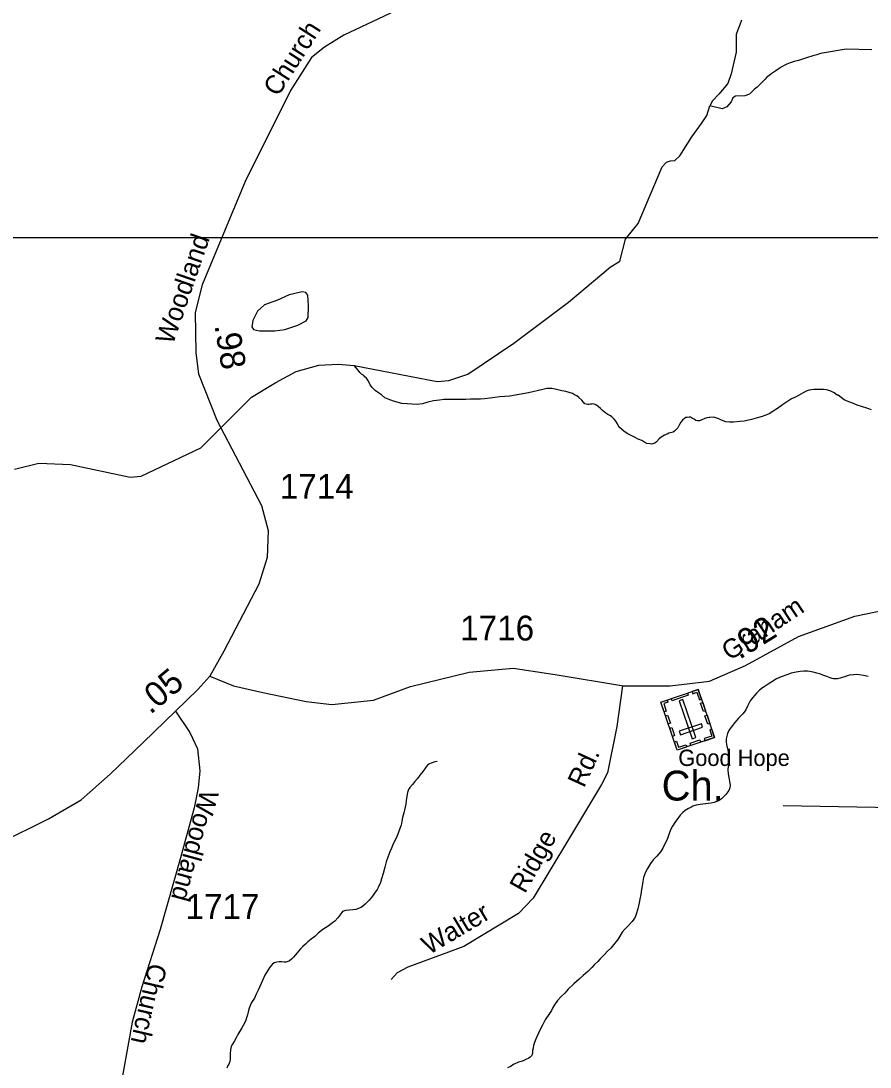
# Model space of a CAD drawing. Extents: x 2056842 to 2160602, y 826753 to 1016856.
# Drawn here: x 2126740 to 2131011, y 836629 to 841891 of the extents above; entities that cross this region are included whole.
import ezdxf

# ---------------------------------------------------------------- set-up
doc = ezdxf.new("R2010")
doc.units = 0
for name, color, linetype in [('Exist Cultural Cemetery CELL', 7, 'Continuous'), ('Exist Cultural Cemetery Label', 7, 'Continuous'), ('Exist Cultural Church with Cemetery Label', 7, 'Continuous'), ('Exist Hydrographic Creek Single Shore', 7, 'Continuous'), ('Exist Hydrographic Misc Water Feature', 7, 'Continuous'), ('Exist Road Non-System Type 51', 7, 'Continuous'), ('Exist Road Non-System Type 51 Label', 7, 'Continuous'), ('Exist Road Secondary Mileage Hundredths English Label', 7, 'Continuous'), ('Exist Road Secondary Type 41 Attributed', 7, 'Continuous'), ('Exist Road Secondary Type 51 Attributed', 7, 'Continuous'), ('Exist Road Secondary Type 51 Label', 7, 'Continuous'), ('Exist Road Secondary Type 51 Number Label', 7, 'Continuous'), ('Map Preparation Inset Cut Line', 7, 'Continuous')]:
    doc.layers.add(name, color=color, linetype=linetype)

msp = doc.modelspace()

# ---------------------------------------------------------------- linework, layer by layer
at = {"layer": 'Exist Cultural Cemetery CELL'}
for points in [[(2130229.4, 838287.4), (2130041, 838223.2), (2129958.9, 838464.3), (2130147.4, 838528.4)], [(2130096.7, 838499), (2130016.4, 838471.7), (2130012.7, 838482.5), (2130093, 838509.8)], [(2130116.1, 838517.7), (2130119.8, 838506.8), (2130140.6, 838513.9), (2130153.6, 838475.7), (2130164.2, 838479.3), (2130147.5, 838528.4)], [(2129990.3, 838474.9), (2129994, 838464.1), (2129973.2, 838457), (2129986.2, 838418.7), (2129975.6, 838415.1), (2129958.9, 838464.3)], [(2130116.8, 838280), (2130134.5, 838286), (2130069.1, 838478), (2130051.4, 838471.9)], [(2130170, 838462.2), (2130183.9, 838421.2), (2130173.1, 838417.6), (2130159.2, 838458.6)], [(2129993, 838399.5), (2130006.9, 838358.5), (2129996.2, 838354.8), (2129982.2, 838395.8)], [(2130191.6, 838398.6), (2130205.6, 838357.6), (2130194.8, 838353.9), (2130180.8, 838394.9)], [(2130014.2, 838337.1), (2130028.2, 838296.1), (2130017.4, 838292.4), (2130003.4, 838333.4)], [(2130168.9, 838338.7), (2130162.9, 838356.3), (2130051.4, 838318.4), (2130057.4, 838300.7)], [(2130215.5, 838328.4), (2130204.7, 838324.7), (2130215.1, 838294.2), (2130176.7, 838281.2), (2130180.3, 838270.6), (2130229.4, 838287.4)], [(2130026.9, 838264.2), (2130037.7, 838267.9), (2130048.1, 838237.4), (2130086.4, 838250.5), (2130090, 838240), (2130040.9, 838223.2)], [(2130159.3, 838263.5), (2130110.3, 838246.8), (2130106.6, 838257.6), (2130155.7, 838274.3)]]:
    msp.add_lwpolyline(points, close=True, dxfattribs=at)
at = {"layer": 'Exist Hydrographic Creek Single Shore'}
for points in [[(2130364.2, 841893.5), (2130356.6, 841870.8), (2130346.4, 841845.5), (2130337.4, 841821.7), (2130337.3, 841733.5), (2130313, 841624.3), (2130296.5, 841575.8), (2130250.2, 841521.8), (2130218.3, 841488.7), (2130205.7, 841463.9)], [(2131020.7, 841745.4), (2130891.7, 841748.7), (2130762.2, 841727), (2130743.8, 841720.8), (2130723.7, 841714.6), (2130691.9, 841704.8), (2130672, 841698.4), (2130651.9, 841692.2), (2130630, 841686.1), (2130609.3, 841679.1), (2130592.9, 841672.3), (2130576.4, 841665), (2130564.8, 841658.7), (2130549.4, 841648.4), (2130537.3, 841639.7), (2130526.8, 841632.4), (2130516.8, 841625.4), (2130504.1, 841615.9), (2130492.8, 841607.1), (2130484.2, 841598.2), (2130474.9, 841588.7), (2130464.7, 841578.9), (2130461.2, 841575), (2130452, 841565.8), (2130443, 841557.8), (2130436.6, 841552.3), (2130430, 841546.8), (2130405.6, 841521.5), (2130381.4, 841514), (2130334, 841512.9), (2130320.8, 841504.1), (2130313, 841484.3), (2130291, 841457.8), (2130267.9, 841449), (2130205.7, 841463.9)], [(2126707.9, 839636.5), (2126830.8, 839666.6), (2126989.2, 839659.6), (2127290.2, 839596.6), (2127344.8, 839600.8), (2127645.7, 839743.5), (2127900.6, 839997.6), (2128022.3, 840071.8), (2128124.4, 840127.8), (2128238.6, 840159.4), (2128335.9, 840164.3), (2128415.8, 840157.8), (2128834.2, 840076.7), (2128892.5, 840081.6), (2128987.3, 840113.2), (2129219.6, 840270.3), (2129495.2, 840476.9), (2129704.6, 840652.3), (2129752, 840682.5), (2129780.7, 840792.8), (2129845.7, 840871.1), (2129964.8, 841156.4), (2129987.9, 841180.7), (2130007.7, 841187.3), (2130029.8, 841188.3), (2130055.1, 841212.5), (2130114.6, 841307.4), (2130164.2, 841374.6), (2130190.7, 841415.5), (2130205.7, 841463.9)], [(2129919.5, 839763.4), (2129913.1, 839761.9), (2129905.1, 839763.9), (2129889.1, 839765.9), (2129873.1, 839773.6), (2129863.5, 839779.6), (2129845.2, 839787.2), (2129826.8, 839796.5), (2129809.1, 839805.3), (2129792.7, 839814.6), (2129774.7, 839826.3), (2129760.5, 839838.2), (2129748.4, 839849.7), (2129740.7, 839863.9), (2129732.5, 839878.1), (2129724.3, 839888.3), (2129711.7, 839899.9), (2129706, 839904), (2129691.6, 839911.9), (2129682, 839917.8), (2129665.6, 839931.3), (2129655.8, 839941.3), (2129643.9, 839951.2), (2129635.5, 839957.3), (2129629.3, 839961.5), (2129623.4, 839963.2), (2129615.6, 839964.8), (2129609.6, 839962.4), (2129605.3, 839962.7), (2129599.2, 839961.2), (2129591.4, 839960.7), (2129583.2, 839962.4), (2129577.2, 839964.9), (2129561.6, 839982.7), (2129546.9, 839996.7), (2129536.6, 840004.3), (2129524.9, 840010.6), (2129514.9, 840016.2), (2129480.9, 840026.2), (2129470.8, 840027.7), (2129461, 840029.6), (2129440.9, 840035.9), (2129426.9, 840039.2), (2129411.1, 840041.6), (2129384.9, 840042.7), (2129364.8, 840036.8), (2129293.2, 840020.1), (2129199.1, 840003.1), (2129174.9, 840001.1), (2129149.1, 839999.3), (2129123.2, 839996.3), (2129100.9, 839992.8), (2129071.2, 839990), (2129051.7, 839988.1), (2129035.5, 839987.7), (2129013.3, 839988.2), (2129001.4, 839987.6), (2128977.2, 839987.2), (2128945.3, 839987.1), (2128919.2, 839986.6), (2128891.1, 839986.4), (2128867.3, 839986), (2128845.4, 839984), (2128815.7, 839980), (2128787.6, 839973.7), (2128759.7, 839965.4), (2128735.7, 839960.9), (2128655.5, 839966.9), (2128613.7, 839978.1), (2128587.6, 839987.8), (2128571.4, 839995.5), (2128553, 840010), (2128533.1, 840023.2), (2128521.2, 840031.1), (2128506.9, 840047), (2128497, 840061.1), (2128492.9, 840069.5), (2128484.5, 840083.7), (2128478.6, 840093.5), (2128470.4, 840100.8), (2128464.6, 840107), (2128452.7, 840114.5), (2128444.3, 840123), (2128436.1, 840134.4), (2128415.8, 840157.8)], [(2131019.4, 839935.3), (2130999.5, 839941.5), (2130969.1, 839951), (2130947.2, 839958.7), (2130927.3, 839966.6), (2130905.1, 839974.5), (2130880.7, 839984.2), (2130851.2, 840007.8), (2130846.5, 840007.7), (2130830.5, 840019.4), (2130814.5, 840028), (2130798.5, 840033.2), (2130790.7, 840035.2), (2130776.6, 840036.9), (2130760.6, 840037.3), (2130746.4, 840036.6), (2130728.6, 840037.3), (2130716.3, 840035.1), (2130704.4, 840032.8), (2130690.5, 840028.1), (2130674.9, 840020.3), (2130662.8, 840014), (2130639, 839999.7), (2130616.6, 839990.1), (2130591.4, 839973.7), (2130571.1, 839959.3), (2130545.5, 839940.9), (2130523.7, 839927.5), (2130507.5, 839917), (2130495.5, 839910.7), (2130468, 839900.7), (2130438, 839892.2), (2130415.7, 839886.3), (2130377.8, 839877.8), (2130355.8, 839875.9), (2130324.4, 839873.3), (2130303.9, 839872.8), (2130286.1, 839875.1), (2130264.4, 839882.8), (2130250, 839888.6), (2130235.9, 839894.8), (2130226.2, 839898.3), (2130205.7, 839896.2), (2130202, 839896.3), (2130189.7, 839894.1), (2130179.7, 839890.3), (2130165.9, 839883.9), (2130154.2, 839880), (2130144, 839879.5), (2130134.2, 839881.4), (2130126.2, 839887.1), (2130118, 839891.6), (2130107.9, 839897.6), (2130102, 839897.6), (2130091.9, 839896.7), (2130083.7, 839895.5), (2130080, 839893.3), (2130067.9, 839882.5), (2130060.1, 839873.1), (2130052.1, 839861), (2130044.3, 839844.7), (2130036.3, 839834.9), (2130028.8, 839828.4), (2130020.6, 839822.7), (2130014.8, 839820.4), (2130006.8, 839818.3), (2129998.8, 839816.7), (2129990.8, 839812.2), (2129976.7, 839806.6), (2129968.7, 839801.8), (2129961.1, 839796.4), (2129950.6, 839788.3), (2129936.9, 839773.7), (2129929.1, 839767.6), (2129919.5, 839763.4)], [(2131002.3, 838592.8), (2130979.2, 838599.2), (2130957, 838602.1), (2130942.1, 838603.2), (2130927.9, 838602.5), (2130908.4, 838600.5), (2130896.3, 838596.7), (2130884.4, 838592), (2130871.9, 838588.2), (2130860.2, 838584.3), (2130847.9, 838582.1), (2130838.9, 838581.5), (2130828.3, 838581.8), (2130820.5, 838583.4), (2130811.2, 838586.1), (2130794, 838593.1), (2130774.1, 838601), (2130758.1, 838607), (2130744.2, 838610.4), (2130725.9, 838615.2), (2130707.9, 838618.7), (2130696.2, 838620.5), (2130677.9, 838620), (2130659.7, 838617.9), (2130639.8, 838616.1), (2130614.2, 838609.8), (2130592.4, 838601.4), (2130564.3, 838591.4), (2130540.6, 838581.2), (2130516.6, 838567), (2130498.7, 838555.1), (2130478.8, 838542.2), (2130470.6, 838536.6), (2130455.1, 838524.7), (2130441.1, 838511.8), (2130429.4, 838498.2), (2130419.4, 838485.9), (2130409.1, 838471.2), (2130403.4, 838461.6), (2130395.6, 838443.7), (2130386, 838426.1), (2130378, 838413.9), (2130371.4, 838405.1), (2130360.1, 838393.8), (2130350.3, 838383.2), (2130340.6, 838373.7), (2130330.6, 838361.4), (2130318.9, 838347), (2130312.8, 838338.9), (2130300.9, 838321.3), (2130295.1, 838306.3), (2130291, 838292.7), (2130287.5, 838279.5), (2130287.5, 838263.3), (2130291.6, 838242.7), (2130295.9, 838227.1), (2130297.8, 838210.6), (2130298.2, 838195.5), (2130298.4, 838180.8), (2130298.2, 838167.1), (2130297.4, 838154.6), (2130296.8, 838143.4), (2130296.1, 838123.6), (2130298, 838103.8), (2130300.9, 838086.4), (2130305, 838065), (2130307.6, 838047.2), (2130306.2, 838033.2), (2130301.5, 838021), (2130285.9, 838000.6), (2130275.8, 837989.5), (2130264.2, 837978.3), (2130252.3, 837970.4), (2130240.4, 837964.9), (2130226.4, 837960.1), (2130212.5, 837956.1), (2130196.5, 837954.1), (2130184, 837952.7), (2130170.4, 837951.5), (2130156.5, 837949.2), (2130136.4, 837945.7), (2130120.4, 837940.8), (2130110.2, 837935.5), (2130098.9, 837929.1), (2130081, 837918.8), (2130069.1, 837909.2), (2130056.8, 837896.5), (2130047.2, 837884.2), (2130029.2, 837858.5), (2130017.5, 837840.8), (2130007.8, 837821.9), (2129999.6, 837798.4), (2129992, 837778.1), (2129984.5, 837760.2), (2129974.2, 837742.2), (2129968.5, 837730.1), (2129958.4, 837713.8), (2129948.8, 837701.9), (2129939.1, 837689.5), (2129930.9, 837681.4)], [(2128833.7, 838166.1), (2128821.4, 838163.9), (2128803.8, 838157.6), (2128796, 838153.5), (2128785.5, 838147.4), (2128777.5, 838137.7), (2128771, 838128.9), (2128761.9, 838115.7), (2128747.4, 838097.2), (2128734.7, 838081.3), (2128721.8, 838065), (2128710.5, 838051.2), (2128696.7, 838035), (2128690, 838024.7), (2128685.3, 838010), (2128680.9, 837991.2), (2128678.7, 837970), (2128675.4, 837951), (2128671.7, 837930.5), (2128666, 837908.7), (2128659.8, 837884.8), (2128656.1, 837865.5), (2128652.6, 837846.6), (2128646.7, 837828.8), (2128636, 837800.8), (2128625.2, 837776.5), (2128613.1, 837752.3), (2128603.4, 837730.3), (2128595.4, 837712.5), (2128585.4, 837685.5), (2128578, 837661.9), (2128570, 837634.3), (2128562.2, 837603), (2128554.6, 837575.4), (2128548.7, 837557.6), (2128539.3, 837535.5), (2128531.3, 837521.7), (2128519.4, 837503.2), (2128509.3, 837489.3), (2128492.1, 837469.2), (2128481.8, 837459), (2128472, 837449.1), (2128457.8, 837437.1), (2128450.3, 837432.6), (2128438.2, 837427.1), (2128424.2, 837422.3), (2128410.3, 837420.3), (2128392.2, 837418.2), (2128372.1, 837415.9), (2128362.5, 837413.8), (2128358, 837412), (2128353.7, 837406.6), (2128344.3, 837393.8), (2128334.4, 837379.9), (2128318.4, 837363.7), (2128300.8, 837349.3), (2128285.2, 837337.4), (2128258.9, 837320.7), (2128235.4, 837303.2), (2128217.7, 837286.4), (2128199.7, 837272.9), (2128183.7, 837258.3), (2128171.8, 837247.9), (2128157.9, 837235.8), (2128146, 837223.8), (2128138, 837214.1), (2128130.4, 837203.5), (2128120.3, 837191.6), (2128110.7, 837182.1), (2128102.5, 837174), (2128088.6, 837161.9), (2128082.2, 837159.6), (2128074.6, 837157.1), (2128064.8, 837157.4), (2128050.2, 837159.2), (2128038.7, 837158.9), (2128026.6, 837157.5), (2128014.7, 837152.8), (2128004.5, 837144.6), (2127992.8, 837130.9), (2127983.2, 837119), (2127971.3, 837100.2), (2127967.4, 837092.2), (2127955.5, 837064.4), (2127941.5, 837034.4), (2127933.9, 837016.6), (2127924.1, 836996.1), (2127914.5, 836976.1), (2127900.1, 836953.9), (2127894.2, 836941.8), (2127888.6, 836925.6), (2127884.7, 836913.2), (2127879, 836891.4), (2127875.1, 836877.4), (2127871.4, 836865.3), (2127864.4, 836849.7), (2127851.3, 836827), (2127831.6, 836793), (2127822.2, 836777), (2127814.2, 836761.6)], [(2129930.9, 837681.4), (2129921.1, 837671.2), (2129907.2, 837653.4), (2129891.4, 837627.4), (2129881.9, 837609), (2129872.1, 837582.9), (2129868, 837563.2), (2129864.3, 837541), (2129862, 837523.1), (2129857.9, 837497.8), (2129853, 837473.4), (2129849.1, 837455.3), (2129843.2, 837424.9), (2129835.4, 837398.9), (2129829.9, 837382.7), (2129823.9, 837373.1), (2129813.9, 837360.8), (2129790.7, 837336.7), (2129778.6, 837322.3), (2129764.4, 837307), (2129751.9, 837288.2), (2129741.9, 837271.4), (2129727.3, 837251.8), (2129707, 837227.7), (2129691.2, 837211.8), (2129673.6, 837193), (2129653.7, 837173.2), (2129642, 837160.8), (2129624.2, 837143.2), (2129612.3, 837130.4), (2129592.4, 837110.3), (2129568.6, 837090.4), (2129548.5, 837071.9), (2129521, 837047.7), (2129493, 837021.5), (2129475.5, 837001), (2129457.7, 836983.4), (2129439.6, 836963.4), (2129423.8, 836943.1), (2129414.2, 836925.5), (2129408.3, 836913.4), (2129398.6, 836898.7), (2129376.7, 836867.1), (2129362.9, 836840.4), (2129352.9, 836820.8), (2129343.5, 836800.3), (2129333.6, 836778.6), (2129327.7, 836766.5), (2129321.7, 836748.4), (2129317.8, 836738), (2129316.4, 836724), (2129314.1, 836712.6), (2129314.1, 836700.5), (2129312.3, 836692.2), (2129310.5, 836688), (2129302.3, 836679.9), (2129294.5, 836674.2), (2129280.1, 836666.6), (2129262.7, 836659.6), (2129242.6, 836653.3), (2129220.4, 836643.2), (2129203, 836632.9), (2129186.8, 836624.8)], [(2127814.2, 836761.6), (2127804.1, 836745.3), (2127798.4, 836733.2), (2127794.3, 836716.7), (2127792.7, 836697.1), (2127792.5, 836683.3), (2127792.7, 836666.6), (2127791, 836656.7), (2127785.3, 836644.6), (2127781, 836636.8), (2127775.6, 836624.6)]]:
    msp.add_lwpolyline(points, dxfattribs=at)
at = {"layer": 'Exist Hydrographic Misc Water Feature'}
msp.add_lwpolyline([(2128068.2, 840338), (2128133.3, 840360.1), (2128175.1, 840382.2), (2128185.1, 840398.7), (2128186.2, 840457.2), (2128182.8, 840511.2), (2128172.9, 840524.4), (2128155.3, 840528.8), (2128089.2, 840513.4), (2128030.7, 840485.8), (2127964.6, 840462.7), (2127930.4, 840430.7), (2127907.3, 840384.4), (2127901.8, 840351.3), (2127909.5, 840339.1), (2127940.4, 840332.5), (2128017.5, 840331.4), (2128068.2, 840338)], dxfattribs=at)
at = {"layer": 'Exist Road Non-System Type 51'}
msp.add_line((2131613.2, 837922.1), (2130573.7, 837943.9), dxfattribs=at)
msp.add_lwpolyline([(2129765.6, 838546.1), (2129737.7, 838341.9), (2129690, 838109.1), (2129660.9, 838050.9), (2129493.7, 837773.5), (2129317.2, 837478.3), (2129242.4, 837401.4), (2128968.2, 837235.2), (2128686.8, 837132.3), (2128632.8, 837103.2), (2128601.6, 837069.9)], dxfattribs=at)
at = {"layer": 'Exist Road Secondary Type 41 Attributed'}
msp.add_lwpolyline([(2124639.5, 839356.9), (2124751.8, 839125.5), (2124821.4, 838968.6), (2124883.7, 838787.8), (2124902.4, 838658.9), (2124929.4, 838534.2), (2124979.2, 838430.3), (2125235.1, 838084.5), (2125516.2, 837755.8), (2125642.8, 837626.9), (2125758.1, 837561.5), (2125922.2, 837511.6), (2126017.7, 837503.3), (2126150.7, 837530.3), (2126391.6, 837636.3), (2126878.7, 837878.4), (2127042.8, 837974), (2127188.1, 838102.9), (2127354.3, 838260.9), (2127517, 838418.6)], dxfattribs=at)
at = {"layer": 'Exist Road Secondary Type 51 Attributed'}
for points in [[(2129232.5, 842997.6), (2129236.1, 842897.9), (2129200.8, 842789.8), (2129063.7, 842409.5), (2129014.9, 842265), (2128958.8, 842177.7), (2128873.6, 842080), (2128738.6, 841996.9), (2128364.8, 841818.1), (2128267.1, 841757.9), (2128201.7, 841706.9), (2128095.8, 841540.7), (2127867.3, 841083.4), (2127652.4, 840562.8), (2127617, 840423.5), (2127619.1, 840221.9), (2127633.7, 840115.9), (2127726.1, 839882.1), (2127950.4, 839453.9), (2127983.6, 839327.1), (2127979.5, 839192), (2127936.9, 839058), (2127760.4, 838721.2), (2127689.7, 838594.5)], [(2127689.7, 838594.5), (2127808.5, 838547.2), (2127956.5, 838512.8), (2128175.2, 838467.1), (2128304, 838452.6), (2128512.8, 838474.4), (2128699.7, 838543), (2128994.6, 838615.8), (2129215.8, 838635.5), (2129427.7, 838604.3), (2129770.4, 838546.1), (2130006.1, 838547.2), (2130203.4, 838570), (2130384.1, 838649), (2130652.1, 838794.5), (2130935.6, 838897.4), (2131195.2, 838951.4), (2131436.1, 838986.8), (2131765.4, 839023.1), (2132074.8, 839077.2), (2132379.1, 839113.5)], [(2127517, 838418.6), (2127629.5, 838528), (2127689.7, 838594.5)], [(2127517, 838418.6), (2127590.2, 838312.5), (2127627.6, 838230.3), (2127639.6, 838119.6), (2127632.1, 838032.9), (2127611.9, 837932.7), (2127543.1, 837681.6), (2127440, 837321.2), (2127348.8, 837032.7), (2127299.4, 836854.8), (2127250.5, 836584.6), (2127233.9, 836389.2), (2127243.3, 836194.9), (2127449.9, 835293.9), (2127544.1, 834974.2), (2127552.3, 834948.1)]]:
    msp.add_lwpolyline(points, dxfattribs=at)
at = {"layer": 'Map Preparation Inset Cut Line'}
msp.add_lwpolyline([(2126559.3, 840801.4), (2135707.8, 840801.4), (2135707.8, 826752.8), (2126559.3, 826752.8)], close=True, dxfattribs=at)

# ---------------------------------------------------------------- texts
at = {"layer": 'Exist Cultural Cemetery Label'}
msp.add_text('Ch.', height=150, dxfattribs=at).set_placement((2129963.1, 837969.8))
at = {"layer": 'Exist Cultural Church with Cemetery Label'}
msp.add_text('Good Hope', height=82.02, dxfattribs=at).set_placement((2130046.7, 838143.6))
at = {"layer": 'Exist Road Non-System Type 51 Label'}
for s, rotation, p in [('Rd.', 65.391, (2129572.4, 838029.9)), ('Ridge', 60.5811, (2129275.4, 837497.8)), ('Walter', 30.8255, (2128792.6, 837191.8))]:
    msp.add_text(s, height=95, rotation=rotation, dxfattribs=at).set_placement(p)
at = {"layer": 'Exist Road Secondary Mileage Hundredths English Label'}
for s, rotation, p in [('.98', 279.5361, (2127712.9, 840359.1)), ('.92', 31.8114, (2130354.2, 838676.9)), ('.05', 40.0837, (2127390.9, 838399.4))]:
    msp.add_text(s, height=125, rotation=rotation, dxfattribs=at).set_placement(p)
at = {"layer": 'Exist Road Secondary Type 51 Label'}
for s, rotation, p in [('Church', 57.4768, (2128033, 841505.6)), ('Woodland', 70.9093, (2127504.2, 840258)), ('Graham', 33.3796, (2130304.8, 838670.3)), ('Woodland', 254.7668, (2127644.7, 838030.3)), ('Church', 257.026, (2127383.5, 837156.5))]:
    msp.add_text(s, height=95, rotation=rotation, dxfattribs=at).set_placement(p)
at = {"layer": 'Exist Road Secondary Type 51 Number Label'}
for s, p in [('1714', (2128042.3, 839487.7)), ('1716', (2128949.6, 838774.6)), ('1717', (2127568.1, 837374.4))]:
    msp.add_text(s, height=125, dxfattribs=at).set_placement(p)

doc.saveas('drawing.dxf')
